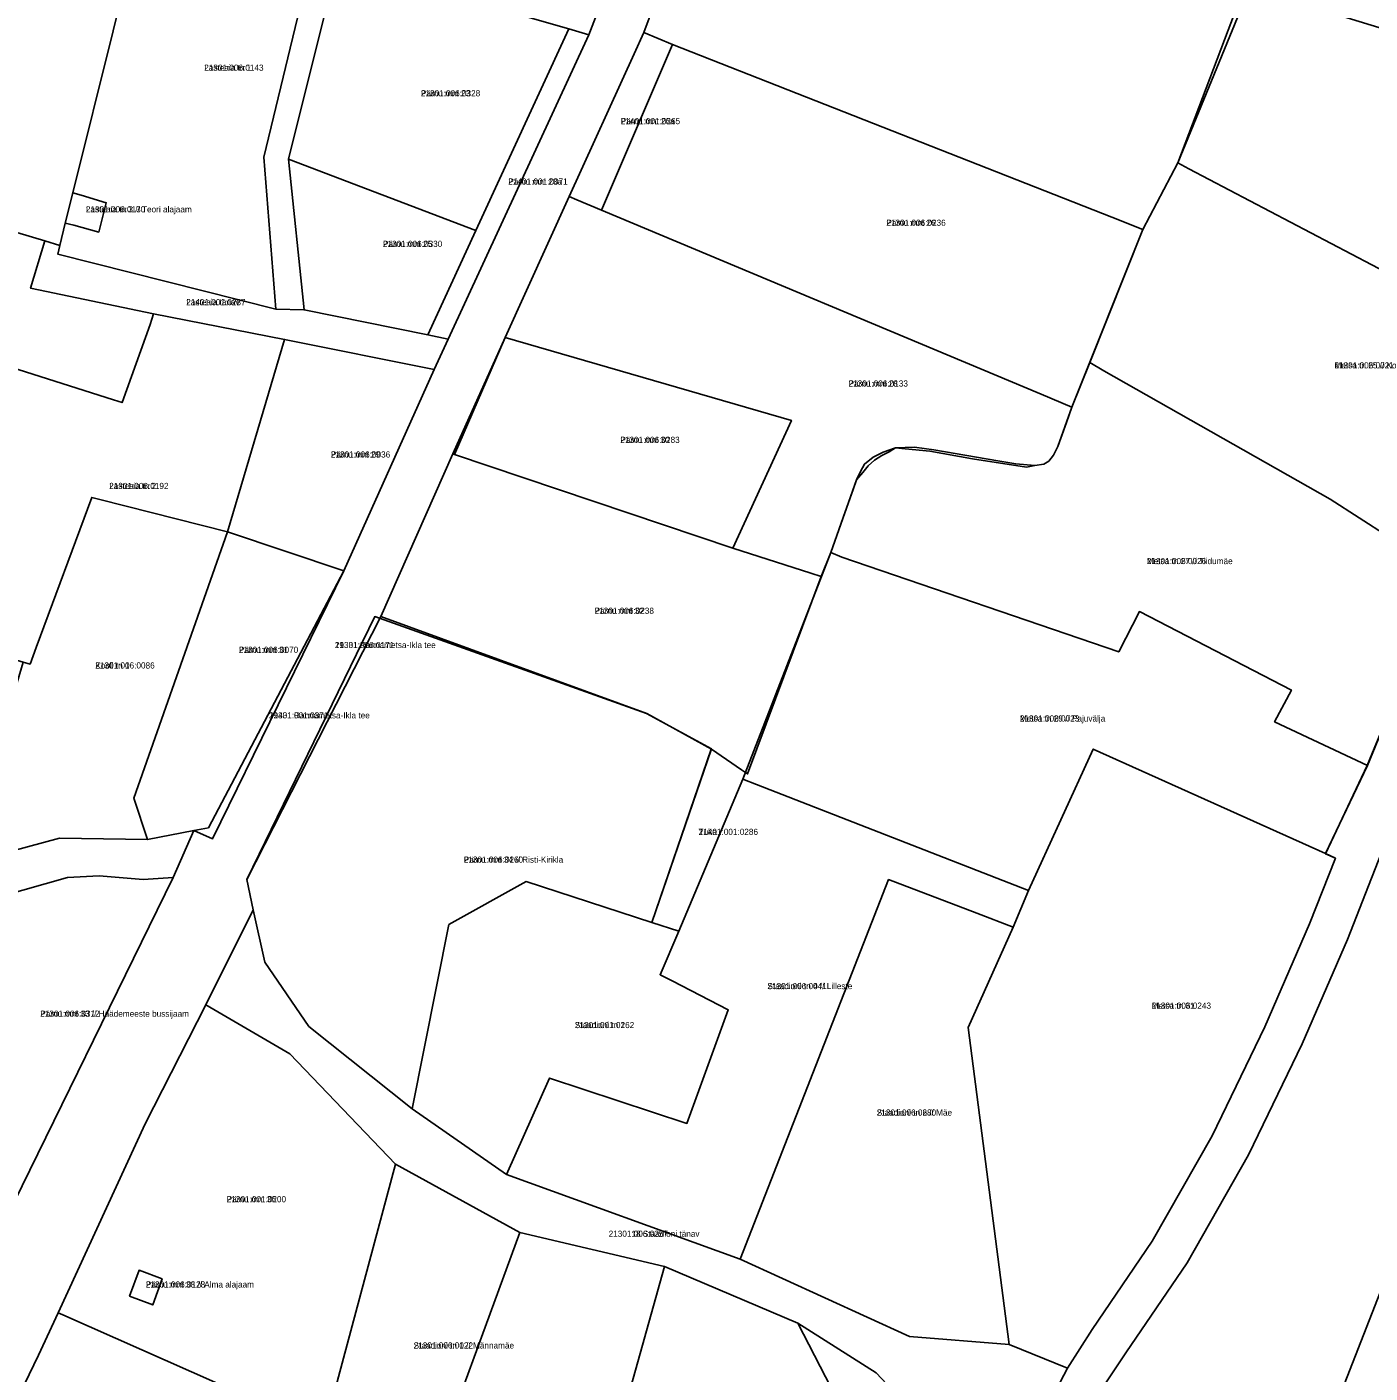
# Model space of a CAD drawing. Extents: x 520985 to 542706, y 6413723 to 6468993.
# Drawn here: x 529383.8 to 529711.9, y 6437602.7 to 6437931.4 of the extents above; entities that cross this region are included whole.
import ezdxf

# ---------------------------------------------------------------- set-up
doc = ezdxf.new("R2010")
doc.units = 0
for name, color, linetype in [('L_AADRESS', 7, 'Continuous'), ('PIIR', 7, 'Continuous'), ('TUNNUS', 7, 'Continuous')]:
    doc.layers.add(name, color=color, linetype=linetype)

msp = doc.modelspace()

# ---------------------------------------------------------------- linework, layer by layer
at = {"layer": 'PIIR'}
for points in [[(529494.97, 6438046.33), (529475.29, 6438004.49), (529464.44, 6437965.12), (529459.65, 6437947.21), (529447.72, 6437899.14), (529451.53, 6437862.34), (529444.58, 6437862.53), (529441.66, 6437899.62), (529462.89, 6437987.32), (529469.27, 6438013.77), (529477.3, 6438034.08), (529483.82, 6438050.7)], [(529351.31, 6437939.66), (529370, 6438022.07), (529420.28, 6438012.48), (529422.05, 6438012.14), (529422.58, 6438003.55), (529420.46, 6437993.36), (529414.69, 6437970.14), (529395.03, 6437890.95), (529393.19, 6437883.54), (529391.83, 6437878.07), (529388.15, 6437879.17), (529301.38, 6437905.02), (529295.93, 6437909), (529244.39, 6437910.92), (529246.7, 6437940.18), (529281.7, 6437955.61)], [(529417.59, 6437971.17), (529462.89, 6437987.32), (529441.66, 6437899.62), (529444.58, 6437862.53), (529391.36, 6437875.91), (529391.83, 6437878.07), (529393.19, 6437883.54), (529395.23, 6437883.02), (529401.37, 6437881.35), (529403.18, 6437888.5), (529397.05, 6437890.35), (529395.03, 6437890.95), (529414.69, 6437970.14)], [(529553.9, 6437981.9), (529572.3, 6437976.9), (529595.7, 6437970.8), (529632.3, 6437959), (529681.5, 6437941.9), (529664.95, 6437898.21), (529656.4, 6437882), (529648.87, 6437884.95), (529541.5, 6437927.16), (529534.5, 6437930.04)], [(529497.54, 6437975.11), (529534.42, 6437964.27), (529521.09, 6437929.51), (529516.16, 6437930.95), (529459.65, 6437947.21), (529464.44, 6437965.12), (529492.64, 6437957.39)], [(529516.16, 6437930.95), (529493.5, 6437881.76), (529447.72, 6437899.14), (529459.65, 6437947.21)], [(529664.95, 6437898.21), (529682.77, 6437941.59), (529706.38, 6437933.63), (529763.71, 6437916.16), (529777.81, 6437890.59), (529762.03, 6437847.28), (529667.69, 6437896.77)], [(529516.16, 6437930.95), (529521.09, 6437929.51), (529486.73, 6437855.22), (529481.72, 6437856.27), (529493.5, 6437881.76)], [(529541.5, 6437927.16), (529524.19, 6437886.7), (529518.16, 6437889.23), (529516.29, 6437890.01), (529532.16, 6437924.86), (529534.5, 6437930.04)], [(529541.5, 6437927.16), (529648.87, 6437884.95), (529656.4, 6437882), (529639.12, 6437838.57), (529631.6, 6437841.72), (529524.19, 6437886.7)], [(529388.15, 6437879.17), (529384.71, 6437867.62), (529414.74, 6437861.34), (529413.94, 6437858.8), (529407.04, 6437839.69), (529404.93, 6437840.34), (529379.87, 6437848.32), (529362.18, 6437782.43), (529343.12, 6437788), (529297.83, 6437799.46), (529295.59, 6437792.04), (529272.08, 6437796.93), (529301.38, 6437905.02)], [(529493.5, 6437881.76), (529481.72, 6437856.27), (529451.53, 6437862.34), (529447.72, 6437899.14)], [(529643.45, 6437849.45), (529656.4, 6437882), (529664.95, 6437898.21), (529667.69, 6437896.77), (529762.03, 6437847.28), (529730.55, 6437797.87), (529702.18, 6437816.07), (529646.94, 6437847.45)], [(529393.19, 6437883.54), (529395.03, 6437890.95), (529397.05, 6437890.35), (529403.18, 6437888.5), (529401.37, 6437881.35), (529395.23, 6437883.02)], [(529516.29, 6437890.01), (529518.16, 6437889.23), (529524.19, 6437886.7), (529631.6, 6437841.72), (529639.12, 6437838.57), (529635.63, 6437829.01), (529634.61, 6437826.83), (529633.45, 6437825.35), (529632.21, 6437824.65), (529630.06, 6437824.31), (529625.43, 6437824.7), (529620.99, 6437825.47), (529605.35, 6437828.15), (529600.62, 6437828.77), (529595.99, 6437828.65), (529592.96, 6437827.6), (529590.55, 6437826.34), (529588.46, 6437824.66), (529587.42, 6437822.87), (529586.51, 6437820.81), (529585.66, 6437818.48), (529583.7, 6437812.98), (529580.17, 6437803.09), (529577.84, 6437797.21), (529575.28, 6437798.04), (529556.24, 6437804.15), (529570.59, 6437835.36), (529500.62, 6437855.55)], [(529391.83, 6437878.07), (529391.36, 6437875.91), (529444.58, 6437862.53), (529451.53, 6437862.34), (529481.72, 6437856.27), (529486.73, 6437855.22), (529483.33, 6437847.76), (529446.77, 6437855.13), (529414.74, 6437861.34), (529384.71, 6437867.62), (529388.15, 6437879.17)], [(529446.77, 6437855.13), (529432.79, 6437808.09), (529401.62, 6437816.02), (529399.65, 6437816.53), (529386.08, 6437779.89), (529384.58, 6437775.84), (529382.9, 6437776.33), (529362.18, 6437782.43), (529379.87, 6437848.32), (529404.93, 6437840.34), (529407.04, 6437839.69), (529413.94, 6437858.8), (529414.74, 6437861.34)], [(529432.79, 6437808.09), (529446.77, 6437855.13), (529483.33, 6437847.76), (529461.26, 6437798.64)], [(529500.62, 6437855.55), (529570.59, 6437835.36), (529556.24, 6437804.15), (529488.29, 6437827.04)], [(529650.56, 6437778.79), (529582.91, 6437801.98), (529580.17, 6437803.09), (529586.51, 6437820.81), (529588.04, 6437822.62), (529589.35, 6437824.22), (529590.91, 6437825.6), (529592.66, 6437826.78), (529594.46, 6437827.64), (529595.99, 6437828.65), (529598.4, 6437828.44), (529604.43, 6437827.84), (529614.84, 6437825.92), (529627.98, 6437823.94), (529630.06, 6437824.31), (529632.21, 6437824.65), (529633.45, 6437825.35), (529634.61, 6437826.83), (529635.63, 6437829.01), (529637.74, 6437834.8), (529639.12, 6437838.57), (529643.45, 6437849.45), (529646.94, 6437847.45), (529702.18, 6437816.07), (529730.55, 6437797.87), (529711.29, 6437751.04), (529688.62, 6437761.75), (529692.71, 6437769.5), (529655.6, 6437788.64)], [(529470.25, 6437787.45), (529487.82, 6437827.2), (529488.29, 6437827.04), (529556.24, 6437804.15), (529575.28, 6437798.04), (529577.84, 6437797.21), (529559.88, 6437749.01), (529558.38, 6437750.04), (529551.08, 6437755.02), (529535.22, 6437763.8)], [(529391.8, 6437733.35), (529368.25, 6437726.95), (529368.71, 6437728.63), (529382.9, 6437776.33), (529384.58, 6437775.84), (529386.08, 6437779.89), (529399.65, 6437816.53), (529401.62, 6437816.02), (529432.79, 6437808.09), (529409.93, 6437743.09), (529413.23, 6437732.98)], [(529432.79, 6437808.09), (529461.26, 6437798.64), (529428.16, 6437735.88), (529424.61, 6437735.19), (529413.23, 6437732.98), (529409.93, 6437743.09)], [(529558.7, 6437747.73), (529580.17, 6437803.09), (529582.91, 6437801.98), (529650.56, 6437778.79), (529655.6, 6437788.64), (529692.71, 6437769.5), (529688.62, 6437761.75), (529711.29, 6437751.04), (529701.04, 6437729.54), (529644.31, 6437755.07), (529628.47, 6437720.51), (529562.08, 6437746.42)], [(529424.61, 6437735.19), (529428.16, 6437735.88), (529461.26, 6437798.64), (529429.18, 6437733.16)], [(529452.7, 6437687.31), (529441.95, 6437703.05), (529439.1, 6437715.84), (529437.56, 6437723.19), (529468.8, 6437787.43), (529535.14, 6437763.77), (529551.02, 6437755.13), (529536.47, 6437712.76), (529505.81, 6437722.71), (529486.9, 6437712.23), (529477.9, 6437667.24)], [(529706.39, 6437708.59), (529718.34, 6437738.91), (529734.32, 6437787.58), (529735.82, 6437786.79), (529781.5, 6437756.45), (529750.54, 6437714.92), (529697.5, 6437579.03), (529647.26, 6437600.06), (529652.25, 6437607.61), (529667.23, 6437629.63), (529682.24, 6437655.99), (529695.33, 6437683.12)], [(529558.7, 6437747.73), (529543.04, 6437710.63), (529536.47, 6437712.76), (529551, 6437755.07), (529551.08, 6437755.02), (529558.38, 6437750.04), (529559.34, 6437749.38)], [(529638.04, 6437603.9), (529623.79, 6437609.64), (529613.72, 6437687.1), (529624.78, 6437711.62), (529628.47, 6437720.51), (529644.31, 6437755.07), (529701.04, 6437729.54), (529703.46, 6437728.43), (529697.15, 6437712.42), (529686.23, 6437687.28), (529673.38, 6437660.64), (529658.74, 6437634.92), (529644.02, 6437613.29)], [(529750.54, 6437714.92), (529998.22, 6437756.92), (529923.47, 6437683.57), (530146.02, 6437604.93), (530147.33, 6437604.47), (530155.07, 6437506.03), (530159.12, 6437436.53), (530158.06, 6437436.76), (529897.15, 6437494.43), (529892.18, 6437495.54), (529696.58, 6437539.38), (529696.86, 6437551.56), (529697.5, 6437579.03)], [(529500.95, 6437651.15), (529511.49, 6437674.73), (529545.06, 6437663.67), (529555.13, 6437691.42), (529541.44, 6437698.44), (529538.48, 6437699.96), (529543.04, 6437710.63), (529558.7, 6437747.73), (529562.08, 6437746.42), (529628.47, 6437720.51), (529624.78, 6437711.62), (529615.89, 6437715), (529594.31, 6437723.2), (529558.07, 6437630.51)], [(529419.5, 6437723.75), (529376.73, 6437636.48), (529372.86, 6437639.26), (529360.79, 6437647.88), (529354.62, 6437645.63), (529360.79, 6437712.79), (529360.94, 6437714.44), (529393.68, 6437723.74), (529401.48, 6437724.11), (529412.24, 6437723.24)], [(529536.47, 6437712.76), (529543.04, 6437710.63), (529538.48, 6437699.96), (529541.44, 6437698.44), (529555.13, 6437691.42), (529545.06, 6437663.67), (529511.49, 6437674.73), (529500.95, 6437651.15), (529477.9, 6437667.24), (529486.9, 6437712.23), (529505.81, 6437722.71)], [(529594.31, 6437723.2), (529615.89, 6437715), (529624.78, 6437711.62), (529613.72, 6437687.1), (529623.79, 6437609.64), (529599.46, 6437611.63), (529558.07, 6437630.51)], [(529439.1, 6437715.84), (529441.95, 6437703.05), (529452.7, 6437687.31), (529477.9, 6437667.24), (529500.95, 6437651.15), (529558.07, 6437630.51), (529599.46, 6437611.63), (529623.79, 6437609.64), (529638.04, 6437603.9), (529613.03, 6437556.07), (529609.3, 6437578.86), (529603.16, 6437590.14), (529591.25, 6437602.78), (529572.11, 6437614.84), (529539.53, 6437628.69), (529504.25, 6437637.04), (529473.84, 6437653.71), (529448.05, 6437680.68), (529427.51, 6437692.64)], [(529412.72, 6437663.56), (529427.51, 6437692.64), (529448.05, 6437680.68), (529473.84, 6437653.71), (529452.33, 6437573.52), (529438, 6437535.65), (529412, 6437546.15), (529414.78, 6437551.91), (529424.06, 6437571.15), (529438.12, 6437563.69), (529446.39, 6437593.29), (529436.86, 6437597.27), (529392.55, 6437616.89), (529391.41, 6437617.39)], [(529473.84, 6437653.71), (529504.25, 6437637.04), (529480.34, 6437571.9), (529477.98, 6437565.22), (529452.33, 6437573.52)], [(529504.25, 6437637.04), (529539.53, 6437628.69), (529522.73, 6437568.48), (529521.09, 6437561.12), (529480.34, 6437571.9)], [(529416.83, 6437625.66), (529414.56, 6437619.34), (529408.89, 6437621.5), (529411.21, 6437627.79)], [(529411.21, 6437627.79), (529408.89, 6437621.5), (529414.56, 6437619.34), (529416.83, 6437625.66)], [(529539.53, 6437628.69), (529572.11, 6437614.84), (529580.25, 6437599.06), (529559.31, 6437556.39), (529522.73, 6437568.48)], [(529391.41, 6437617.39), (529392.55, 6437616.89), (529436.86, 6437597.27), (529424.06, 6437571.15), (529414.78, 6437551.91), (529400.91, 6437558.65), (529395.86, 6437563.08), (529371.11, 6437574.21), (529370.75, 6437574.37), (529386.64, 6437607.06)]]:
    msp.add_lwpolyline(points, close=True, dxfattribs=at)
for points in [[(529553.9, 6437981.9), (529534.5, 6437930.04), (529532.16, 6437924.86), (529516.29, 6437890.01), (529500.62, 6437855.55), (529487.82, 6437827.2), (529470.25, 6437787.45), (529437.56, 6437723.19), (529439.1, 6437715.84), (529427.51, 6437692.64), (529412.72, 6437663.56), (529391.41, 6437617.39), (529386.64, 6437607.06), (529370.75, 6437574.37), (529354.9, 6437541.73), (529343.15, 6437517.88), (529311.45, 6437453.96), (529287.5, 6437404.85), (529277.5, 6437385.17), (529266.58, 6437363.72)], [(529171.7, 6437219.39), (529245.83, 6437371.03), (529273.22, 6437425.26), (529376.73, 6437636.48), (529419.5, 6437723.75), (529424.61, 6437735.19), (529429.18, 6437733.16), (529461.26, 6437798.64), (529483.33, 6437847.76), (529486.73, 6437855.22), (529521.09, 6437929.51), (529534.42, 6437964.27)], [(529574.33, 6437351.44), (529611.12, 6437396.95), (529609.92, 6437452.05), (529613.03, 6437556.07), (529638.04, 6437603.9), (529644.02, 6437613.29), (529658.74, 6437634.92), (529673.38, 6437660.64), (529686.23, 6437687.28), (529697.15, 6437712.42), (529703.46, 6437728.43), (529701.06, 6437729.52), (529711.27, 6437751.05), (529730.55, 6437797.86)], [(529718.34, 6437738.91), (529706.39, 6437708.59), (529695.33, 6437683.12), (529682.24, 6437655.99), (529667.23, 6437629.63), (529652.25, 6437607.61), (529647.26, 6437600.06), (529621.43, 6437556.07), (529621.42, 6437554.61), (529621.14, 6437525.06), (529620.92, 6437496.54), (529622.82, 6437411), (529663.84, 6437327.4)], [(529176.58, 6437665.99), (529231.94, 6437682.87), (529256.64, 6437690.82), (529263.64, 6437692.6), (529298.42, 6437703.61), (529335.18, 6437716.53), (529368.25, 6437726.95), (529391.8, 6437733.35), (529413.23, 6437732.98), (529424.61, 6437735.19), (529419.5, 6437723.75), (529412.24, 6437723.24), (529401.48, 6437724.11), (529393.68, 6437723.74), (529360.94, 6437714.44), (529323.43, 6437702.38), (529320.68, 6437701.47), (529309.82, 6437697.8), (529289.9, 6437691.09), (529286.09, 6437689.84), (529260.16, 6437681.53), (529218.21, 6437668.23), (529207.04, 6437664.8), (529181.26, 6437657.64)], [(529580.25, 6437599.06), (529572.11, 6437614.84), (529591.25, 6437602.78), (529603.16, 6437590.14)]]:
    msp.add_lwpolyline(points, dxfattribs=at)

# ---------------------------------------------------------------- texts
at = {"layer": 'L_AADRESS'}
for s, p in [('Lasteaia tn 1', (529427.12, 6437920.74)), ('Pärnu mnt 23', (529480.05, 6437914.49)), ('Pärnu mnt 26a', (529528.89, 6437907.69)), ('Pärnu mnt 23a', (529501.41, 6437892.93)), ('Lasteaia tn 3 // Teori alajaam', (529398.21, 6437886.15)), ('Pärnu mnt 26', (529593.77, 6437882.87)), ('Pärnu mnt 25', (529470.78, 6437877.71)), ('Lasteaia tänav', (529422.72, 6437863.47)), ('Metsa tn 25 // Kose', (529703.25, 6437848.04)), ('Pärnu mnt 28', (529584.54, 6437843.61)), ('Pärnu mnt 30', (529528.78, 6437829.85)), ('Pärnu mnt 29', (529458.06, 6437826.28)), ('Lasteaia tn 2', (529403.9, 6437818.59)), ('Metsa tn 27 // Tiidumäe', (529657.41, 6437800.24)), ('Pärnu mnt 32', (529522.49, 6437788.11)), ('Pärnu mnt 31', (529435.59, 6437778.57)), ('19331 Rannametsa-Ikla tee', (529459.03, 6437779.74)), ('Kooli tn 1', (529400.52, 6437774.75)), ('19331 Rannametsa-Ikla tee', (529442.93, 6437762.57)), ('Metsa tn 29 // Pajuvälja', (529626.4, 6437761.8)), ('Tuka', (529547.91, 6437734.11)), ('Pärnu mnt 34 // Risti-Kirikla', (529490.53, 6437727.33)), ('Staadioni tn 4 // Lilleste', (529564.71, 6437696.44)), ('Metsa tn 31', (529658.59, 6437691.67)), ('Pärnu mnt 33 // Häädemeeste bussijaam', (529387.06, 6437689.71)), ('Staadioni tn 2', (529517.67, 6437686.93)), ('Staadioni tn 6 // Mäe', (529591.43, 6437665.56)), ('Pärnu mnt 36', (529432.62, 6437644.4)), ('2130118 Staadioni tänav', (529525.92, 6437635.96)), ('Pärnu mnt 38 // Alma alajaam', (529412.86, 6437623.58)), ('Staadioni tn 1 // Männamäe', (529478.29, 6437608.68))]:
    msp.add_text(s, height=1.5, dxfattribs=at).set_placement(p)
at = {"layer": 'TUNNUS'}
for s, p in [('21301:006:0143', (529427.12, 6437920.74)), ('21301:006:0328', (529480.05, 6437914.49)), ('21401:001:0265', (529528.89, 6437907.69)), ('21401:001:0071', (529501.41, 6437892.93)), ('21301:006:0130', (529398.21, 6437886.15)), ('21301:006:0236', (529593.77, 6437882.87)), ('21301:006:0330', (529470.78, 6437877.71)), ('21401:001:0287', (529422.72, 6437863.47)), ('21301:006:0021', (529703.25, 6437848.04)), ('21301:006:0133', (529584.54, 6437843.61)), ('21301:006:0283', (529528.78, 6437829.85)), ('21301:006:0036', (529458.06, 6437826.28)), ('21301:006:0192', (529403.9, 6437818.59)), ('21301:006:0026', (529657.41, 6437800.24)), ('21301:006:0238', (529522.49, 6437788.11)), ('21301:006:0070', (529435.59, 6437778.57)), ('21301:006:0171', (529459.03, 6437779.74)), ('21301:006:0086', (529400.52, 6437774.75)), ('21401:001:0371', (529442.93, 6437762.57)), ('21301:006:0023', (529626.4, 6437761.8)), ('21401:001:0286', (529547.91, 6437734.11)), ('21301:006:0260', (529490.53, 6437727.33)), ('21301:006:0041', (529564.71, 6437696.44)), ('21301:006:0243', (529658.59, 6437691.67)), ('21301:006:0312', (529387.06, 6437689.71)), ('21301:001:0162', (529517.67, 6437686.93)), ('21301:006:0280', (529591.43, 6437665.56)), ('21301:001:0200', (529432.62, 6437644.4)), ('21301:006:0257', (529525.92, 6437635.96)), ('21301:006:0128', (529412.86, 6437623.58)), ('21301:006:0022', (529478.29, 6437608.68))]:
    msp.add_text(s, height=1.5, dxfattribs=at).set_placement(p)

doc.saveas('drawing.dxf')
